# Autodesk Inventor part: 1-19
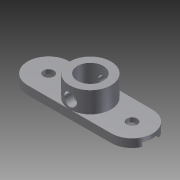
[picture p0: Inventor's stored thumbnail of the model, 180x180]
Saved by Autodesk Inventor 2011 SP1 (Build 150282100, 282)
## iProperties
Created: 2014-02
Part Number: 1-19
Document SubType Name: Modeling
Designer: Administrator
Density: 1 g/cm^3
Author: Administrator
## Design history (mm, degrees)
sketch "草图1"
  geometry: L1 (20.004, -9.857)-(-20.049, -9.946); L2 (-20.049, 9.946)-(20.004, 9.857); A1 r 9.946 centre (-20.072, 0) between (-20.049, 9.946) and (-20.049, -9.946); A2 r 9.857 centre (19.982, 0) between (20.004, -9.857) and (20.004, 9.857); 1 further point
  constraints: 5 end point, 4 point on circle, 3 tangent, 2 centre point
extrude "拉伸1" new body sketch "草图1" distance "d0" = 4; taper "d1" = 0 deg
sketch "草图3"
  geometry: C1 r 9.901 at (0, 0); 1 further point
  constraints: 1 centre point, 1 coincident
extrude "拉伸3" join sketch "草图3" distance "d4" = 10; taper "d5" = 0 deg
sketch "草图4"
  geometry: L1 (-20.004, 9.857)-(20.049, 9.946) reference; L2 (-28.951, -4.088)-(29.197, -3.958); L3 (29.197, 3.958)-(-29.065, 3.827); A1 r 9.857 centre (-19.982, 0) between (-20.004, 9.857) and (-20.004, -9.857) reference; A2 r 9.946 centre (20.072, 0) between (20.049, -9.946) and (20.049, 9.946) reference; 1 further point
  constraints: 4 end point, 4 point on circle, 2 parallel
extrude "拉伸4" cut sketch "草图4" distance "d6" = 2; taper "d7" = 0 deg
sketch "草图5"
  geometry: C1 r 9.901 at (0, 0) reference; C2 r 6.197 at (0, 0)
  constraints: 1 centre point, 1 coincident
extrude "拉伸5" cut sketch "草图5" stored distance "d8" = 2; taper "d9" = 0 deg
hole "Hole1" diameter "d12" = 5; stored, may be unused: countersink angle "d16" = 90 deg, drill point angle "d18" = 118 deg; dims "d10" = 10, "d11" = 10, "d13" = 6, "d14" = 4, "d15" = 2, "d17" = 8
mirror "镜像1"
sketch "草图6"
  geometry: C1 r 3 at (20.072, 8.085); 1 further point
  constraints: 1 centre point
extrude "拉伸6" cut sketch "草图6" stored distance "d20" = 2; taper "d21" = 0 deg
sketch "草图7"
  geometry: C1 r 2 at (20.024, 7.971); 5 further points
  constraints: 2 vertical alignment, 1 centre point
  dimensions: "d22" = 4 diameter of C1
extrude "拉伸7" cut sketch "草图7" stored distance "d23" = 2; taper "d24" = 0 deg
node "实体1"
